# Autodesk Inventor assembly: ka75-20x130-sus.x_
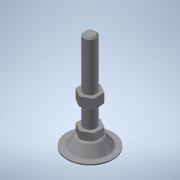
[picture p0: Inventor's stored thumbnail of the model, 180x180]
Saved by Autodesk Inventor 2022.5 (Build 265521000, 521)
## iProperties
Part Number: ka75-20x130-sus.x_
Material: 一般
Document SubType Name: Assembly
Designer: ImaoCorp
Sending System: SOLIDWORKS 2017-2017317
MC: AMD64
MC_MODEL: Intel64 Family 6 Model 60 Stepping 3, GenuineIntel
OS: Windows_NT
FRU: Parasolid Version 29.0, build 201,  4-17-2017
FORMAT: text
GUISE: transmit
KEY: ka75-20x130-sus
FILE: ka75-20x130-sus.x_t
DATE: Mon Jul 01 17:42:26 2019
Author: ImaoCorp
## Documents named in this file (3)
- X:\14_SW2022-Inv2022\00_全2023-1023新製品(TCC)まで\k\ka75-20x130-sus\KA75-20X130-SUS.iam
- X:\14_SW2022-Inv2022\00_全2023-1023新製品(TCC)まで\k\ka75-20x130-sus\ka75-20x130-sus_01.ipt
- X:\14_SW2022-Inv2022\00_全2023-1023新製品(TCC)まで\k\ka75-20x130-sus\ka75-20x130-sus_02.ipt
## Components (2 placed, 2 different names)
1. ka75-20x130-sus_01
2. ka75-20x130-sus_02
